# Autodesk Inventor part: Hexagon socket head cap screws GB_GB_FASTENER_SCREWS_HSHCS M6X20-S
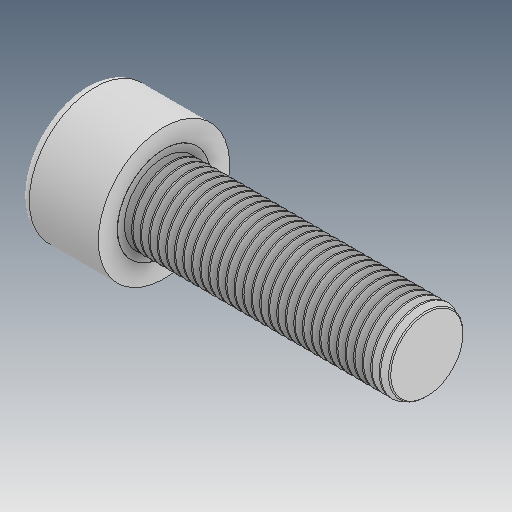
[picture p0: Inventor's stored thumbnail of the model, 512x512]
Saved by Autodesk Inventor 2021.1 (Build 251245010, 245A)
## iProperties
Created: 2013-04
Part Number: Hexagon socket head cap screws GB_GB_FASTENER_SCREWS_HSHCS M6X20-S
Material: Ogólny
Document SubType Name: Modeling
Designer: user
Density: 1 g/cm^3
Appearance: Domyślna
Author: user
Revision Number: ÈÎºÎ
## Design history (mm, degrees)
feature "LPattern10"
node "Bryła1"
